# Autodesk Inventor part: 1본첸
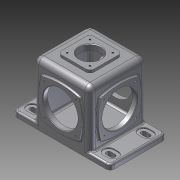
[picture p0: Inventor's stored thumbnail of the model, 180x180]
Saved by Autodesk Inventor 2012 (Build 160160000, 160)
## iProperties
Created: 2012-07
Part Number: 1본첸
Material: Default
Document SubType Name: Modeling
Designer: JANG KYOUNG-IL
Density: 1 g/cm^3
Author: JANG KYOUNG-IL
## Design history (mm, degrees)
sketch "스케치1"
  geometry: L1 (-90, 52.5)-(90, 52.5); L2 (90, 52.5)-(90, -52.5); L3 (90, -52.5)-(-90, -52.5); L4 (-90, -52.5)-(-90, 52.5); 3 further points
  constraints: 8 end point, 2 midpoint, 2 parallel, 1 horizontal, 1 horizontal alignment, 1 perpendicular, 1 vertical alignment
  dimensions: "d0" = 180 distance of L2.end L3.end; "d1" = 105 distance of L3.end L1.start
extrude "돌출1" new body sketch "스케치1" distance "d2" = 10; taper "d3" = 0 deg
sketch "스케치2"
  geometry: L1 (-52.5, 52.5)-(52.5, 52.5); L2 (52.5, 52.5)-(52.5, -52.5); L3 (52.5, -52.5)-(-52.5, -52.5); L4 (-52.5, -52.5)-(-52.5, 52.5); 3 further points
  constraints: 8 end point, 2 midpoint, 2 parallel, 2 perpendicular, 1 horizontal, 1 horizontal alignment, 1 vertical alignment
  dimensions: "d4" = 105 distance of L1.end L1.start
extrude "돌출2" new body sketch "스케치2" distance "d5" = 115; taper "d6" = 0 deg
feature "쉘1" dims "d7" = 10, "d8" = 6
feature "결합1"
  node "솔리드1"
sketch "스케치3"
  geometry: L1 (-30, 30)-(30, 30); L2 (30, 30)-(30, -30); L3 (30, -30)-(-30, -30); L4 (-30, -30)-(-30, 30); 3 further points
  constraints: 8 end point, 2 midpoint, 2 parallel, 2 perpendicular, 1 horizontal, 1 horizontal alignment, 1 vertical alignment
  dimensions: "d9" = 60 distance of L1.end L1.start
extrude "돌출3" join sketch "스케치3" distance "d10" = 5; taper "d11" = 0 deg
sketch "스케치7"
  geometry: C1 r 20 at (0, 0); 1 further point
  constraints: 1 centre point, 1 coincident
  dimensions: "d38" = 40 diameter of C1
extrude "돌출7" cut sketch "스케치7" stored distance "d39" = 3; taper "d40" = 0 deg
fillet "모깎기1" dims "d25" = 8
sketch "스케치8"
  geometry: L1 (0, 0)-(0, 30); A1 r 30 centre (0, 0) between (21.213, 21.213) and (0, 30); 1 further point
  constraints: 2 end point, 2 point on circle, 1 centre point, 1 coincident, 1 vertical
  dimensions: "d41" = 60 diameter of A1; "d42" = 45 deg dimension on point (0, 0) L1.end A1.start
hole "구멍1" sketch "스케치8" at (21.213, 21.213) diameter "d43" = 3.242; stored, may be unused: countersink angle "d47" = 90 deg, drill point angle "d49" = 118 deg; dims "d44" = 6, "d45" = 4, "d46" = 2, "d48" = 9
sketch "스케치4"
  geometry: L1 (-82.502, 17.498)-(-12.498, 17.498); L2 (-12.498, 17.498)-(-12.498, 87.502); L3 (-12.498, 87.502)-(-82.502, 87.502); L4 (-82.502, 87.502)-(-82.502, 17.498); A1 r 125.055 centre (37.555, 52.5) between (-82.502, 87.502) and (-82.502, 17.498); A2 r 125.055 centre (-132.555, 52.5) between (-12.498, 17.498) and (-12.498, 87.502); A3 r 125.055 centre (-47.5, 137.555) between (-82.502, 17.498) and (-12.498, 17.498); A4 r 125.055 centre (-47.5, -32.555) between (-12.498, 87.502) and (-82.502, 87.502); 2 further points
  constraints: 8 end point, 8 point on circle, 4 centre point, 2 equal radius, 2 parallel, 2 perpendicular, 1 horizontal, 1 horizontal alignment, 1 midpoint
  dimensions: "d12" = 99 distance of L3.end L1.end; "d13" = 80 dimension on A2 A1; "d18" = 80 dimension on A4 A3; "d19" = 57.5 horizontal distance of A4.centre point (10, 52.5)
extrude "돌출4" join sketch "스케치4" distance "d20" = 3; taper "d21" = 0 deg
fillet "모깎기2" dims "d26" = 3
sketch "스케치6"
  geometry: C1 r 32.5 at (-47.5, 52.5); 1 further point
  constraints: 1 centre point, 1 horizontal alignment
  dimensions: "d34" = 57.5 distance of C1.centre point (10, 52.5); "d35" = 65 diameter of C1
extrude "돌출6" cut sketch "스케치6" stored distance "d36" = 3; taper "d37" = 0 deg
sketch "스케치9"
  geometry: L1 (-47.5, 52.5)-(-89, 52.5); A1 r 41.5 centre (-47.5, 52.5) between (-89, 52.5) and (-76.845, 81.845); 1 further point
  constraints: 2 end point, 2 point on circle, 1 centre point, 1 horizontal, 1 horizontal alignment
  dimensions: "d53" = 57.5 distance of L1.start point (10, 52.5); "d54" = 83 diameter of A1; "d55" = 45 deg dimension on L1.start L1.end A1.end
hole "구멍2" sketch "스케치9" at (-76.845, 81.845) diameter "d56" = 3.242; stored, may be unused: countersink angle "d60" = 90 deg, drill point angle "d62" = 118 deg; dims "d57" = 6, "d58" = 4, "d59" = 2, "d61" = 9
fillet "모깎기3" dims "d27" = 10
fillet "모깎기4" dims "d28" = 4
fillet "모깎기5" dims "d29" = 8
sketch "스케치10"
  geometry: L1 (-23, 24.5)-(-15, 24.5); L2 (-15, 15.5)-(-23, 15.5); L3 (-15, 30)-(-23, 30); L4 (-23, 10)-(-15, 10); L5 (0, 105)-(0, 0) reference; L6 (0, 0)-(-180, 0) reference; A1 r 4.5 centre (-15, 20) between (-15, 15.5) and (-15, 24.5); A2 r 4.5 centre (-23, 20) between (-23, 24.5) and (-23, 15.5); A3 r 10 centre (-23, 20) between (-23, 30) and (-23, 10); A4 r 10 centre (-15, 20) between (-15, 10) and (-15, 30); 1 further point
  constraints: 8 end point, 8 point on circle, 4 centre point, 4 tangent, 2 parallel, 1 horizontal, 3 other
  dimensions: "d66" = 10 radius of A4; "d67" = 4.5 radius of A1; "d68" = 8 distance of A2.centre A1.centre; "d69" = 15 distance from line of L5 A1.centre; "d70" = 20 distance from line of A1.centre L6
extrude "돌출8" cut sketch "스케치10" distance "d71" = 2; taper "d72" = 0 deg
extrude "돌출9" cut sketch "스케치10" stored distance "d73" = 2; taper "d74" = 0 deg
chamfer "모따기1" distance "d75" = 1; stored, may be unused: second distance "d76" = 2, angle "d77" = 45 deg
fillet "모깎기6" dims "d82" = 3
node "작업 평면1"
sketch "스케치11"
  geometry: 3 further points
  constraints: 1 horizontal alignment, 1 other
  dimensions: "d79" = 57 distance of point (-105, 42.5) point (-48, 42.5)
feature "엠보싱1" sketch "스케치11" dims "d0" = 180, "d1" = 105, "d80" = 1, "d81" = 0
pattern_circular "원형 패턴2" dims angle "d51" = 360 deg
pattern_circular "원형 패턴3" dims angle "d64" = 360 deg
pattern_circular "원형 패턴1" dims "d23" = 180 deg
mirror "대칭1"
mirror "대칭2"
node "솔리드2"
